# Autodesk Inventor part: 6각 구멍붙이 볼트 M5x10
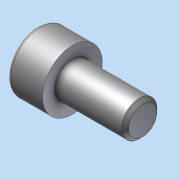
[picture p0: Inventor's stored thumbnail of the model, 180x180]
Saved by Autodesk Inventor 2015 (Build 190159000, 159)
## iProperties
Created: 2026-02
Part Number: 6각 구멍붙이 볼트 M5x10
Material: 일반
Document SubType Name: Modeling
Designer: Administrator
Density: 1 g/cm^3
Appearance: 기본값
Author: Administrator
Author: jhkim
Description: 6각머리 태핑 나사
Creation Date: 2026-01-30
Sending System: Autodesk Inventor 2026
Preprocessor: ST-DEVELOPER v20.1
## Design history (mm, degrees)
node "6각 구멍붙이 볼트 M5x101"
body "Solid1"
node "기준1"
